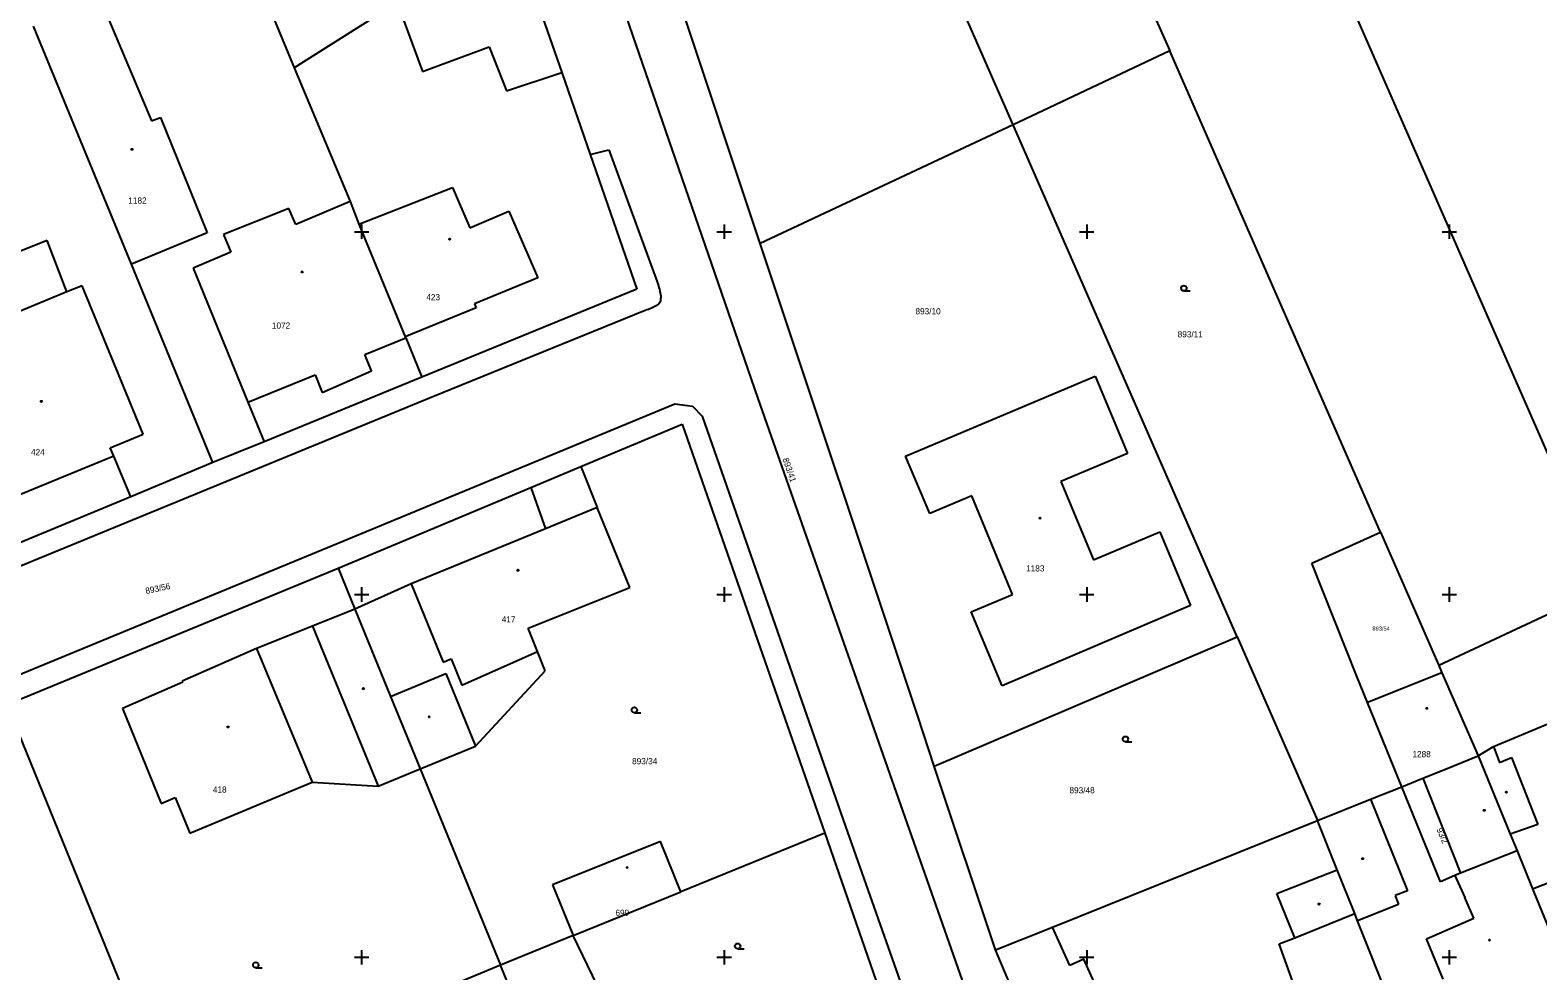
# Model space of a CAD drawing. Extents: x -711081 to -709338, y -1025122 to -1024092.
# Drawn here: x -710097.9 to -709993.9, y -1024600.9 to -1024536.1 of the extents above; entities that cross this region are included whole.
import ezdxf

# ---------------------------------------------------------------- set-up
doc = ezdxf.new("R2010")
doc.units = 0
for name, color, linetype in [('Z_hektometricka_sit', 7, 'Continuous'), ('Z_katastr_cisla_pozemkova', 7, 'Continuous'), ('Z_katastr_cisla_stavebni', 7, 'Continuous'), ('Z_katastr_hranice', 7, 'Continuous'), ('Z_katastr_hranice_katastralniho_uzemi', 7, 'Continuous'), ('Z_katastr_vnitrni_kresba', 7, 'Continuous'), ('Z_katastr_znacky_budov', 7, 'Continuous'), ('Z_katastr_znacky_kultur', 7, 'Continuous')]:
    doc.layers.add(name, color=color, linetype=linetype)

msp = doc.modelspace()

# ---------------------------------------------------------------- linework, layer by layer
at = {"layer": 'Z_hektometricka_sit'}
for p, q in [((-710075, -1024549.5), (-710075, -1024550.5)), ((-710050, -1024549.5), (-710050, -1024550.5)), ((-710025, -1024549.5), (-710025, -1024550.5)), ((-710000, -1024549.5), (-710000, -1024550.5)), ((-710075.5, -1024550), (-710074.5, -1024550)), ((-710050.5, -1024550), (-710049.5, -1024550)), ((-710025.5, -1024550), (-710024.5, -1024550)), ((-710000.5, -1024550), (-709999.5, -1024550)), ((-710075, -1024574.5), (-710075, -1024575.5)), ((-710050, -1024574.5), (-710050, -1024575.5)), ((-710025, -1024574.5), (-710025, -1024575.5)), ((-710000, -1024574.5), (-710000, -1024575.5)), ((-710075.5, -1024575), (-710074.5, -1024575)), ((-710050.5, -1024575), (-710049.5, -1024575)), ((-710025.5, -1024575), (-710024.5, -1024575)), ((-710000.5, -1024575), (-709999.5, -1024575)), ((-710075, -1024599.5), (-710075, -1024600.5)), ((-710050, -1024599.5), (-710050, -1024600.5)), ((-710025, -1024599.5), (-710025, -1024600.5)), ((-710000, -1024599.5), (-710000, -1024600.5)), ((-710075.5, -1024600), (-710074.5, -1024600)), ((-710050.5, -1024600), (-710049.5, -1024600)), ((-710025.5, -1024600), (-710024.5, -1024600)), ((-710000.5, -1024600), (-709999.5, -1024600))]:
    msp.add_line(p, q, dxfattribs=at)
at = {"layer": 'Z_katastr_hranice'}
for p, q in [((-709992.49, -1024566.92), (-710035.72, -1024468.2)), ((-710046, -1024476.54), (-710019.28, -1024537.54)), ((-710030.08, -1024542.63), (-710055.62, -1024484.15)), ((-710047.52, -1024550.81), (-710067.48, -1024490.96)), ((-710071.24, -1024493.19), (-710047.68, -1024561.5)), ((-710093.84, -1024504.36), (-710079.65, -1024538.71)), ((-710063.95, -1024531.09), (-710061.2, -1024539.03)), ((-710094.05, -1024531.53), (-710089.48, -1024542.36)), ((-710072.54, -1024534.22), (-710079.65, -1024538.71)), ((-710094.05, -1024544.53), (-710097.63, -1024535.83)), ((-710019.28, -1024537.54), (-710030.08, -1024542.63)), ((-710004.75, -1024570.7), (-710019.28, -1024537.54)), ((-710079.65, -1024538.71), (-710075.8, -1024547.92)), ((-710061.2, -1024539.03), (-710059.24, -1024544.68)), ((-710089.48, -1024542.36), (-710088.88, -1024542.12)), ((-710088.88, -1024542.12), (-710085.66, -1024550.08)), ((-710030.08, -1024542.63), (-710047.52, -1024550.81)), ((-710015.9, -1024575.01), (-710030.08, -1024542.63)), ((-710090.88, -1024552.23), (-710094.05, -1024544.53)), ((-710059.24, -1024544.68), (-710056.03, -1024553.95)), ((-710080.02, -1024548.39), (-710084.53, -1024550.19)), ((-710079.54, -1024549.5), (-710080.02, -1024548.39)), ((-710075.8, -1024547.92), (-710079.54, -1024549.5)), ((-710075.8, -1024547.92), (-710075.2, -1024549.49)), ((-710075.2, -1024549.49), (-710072, -1024557.25)), ((-710096.68, -1024550.61), (-710106.7, -1024554.58)), ((-710095.32, -1024554.15), (-710096.68, -1024550.61)), ((-710085.66, -1024550.08), (-710090.88, -1024552.23)), ((-710084.53, -1024550.19), (-710084.01, -1024551.4)), ((-710036.65, -1024583.38), (-710047.52, -1024550.81)), ((-710084.01, -1024551.4), (-710086.62, -1024552.5)), ((-710085.25, -1024565.91), (-710090.88, -1024552.23)), ((-710086.62, -1024552.5), (-710082.84, -1024561.75)), ((-710094.27, -1024553.72), (-710095.32, -1024554.15)), ((-710090.06, -1024563.94), (-710094.27, -1024553.72)), ((-710056.03, -1024553.95), (-710070.85, -1024560.03)), ((-710072, -1024557.25), (-710071.96, -1024557.32)), ((-710071.96, -1024557.32), (-710070.85, -1024560.03)), ((-710070.85, -1024560.03), (-710081.73, -1024564.47)), ((-710037.49, -1024565.47), (-710024.42, -1024559.95)), ((-710024.42, -1024559.95), (-710022.2, -1024565.28)), ((-710082.84, -1024561.75), (-710081.73, -1024564.47)), ((-710047.68, -1024561.5), (-710027.15, -1024619.89)), ((-710059.89, -1024566.18), (-710052.89, -1024563.25)), ((-710052.89, -1024563.25), (-710043.05, -1024591.45)), ((-710092.33, -1024564.88), (-710090.06, -1024563.94)), ((-710092.09, -1024565.46), (-710092.33, -1024564.88)), ((-710090.92, -1024568.26), (-710092.09, -1024565.46)), ((-710081.73, -1024564.47), (-710085.25, -1024565.91)), ((-710035.83, -1024569.41), (-710037.49, -1024565.47)), ((-710022.2, -1024565.28), (-710026.79, -1024567.2)), ((-710085.25, -1024565.91), (-710090.92, -1024568.26)), ((-710063.33, -1024567.63), (-710059.89, -1024566.18)), ((-710026.79, -1024567.2), (-710024.54, -1024572.61)), ((-710090.92, -1024568.26), (-710099.63, -1024571.88)), ((-710076.62, -1024573.19), (-710063.33, -1024567.63)), ((-710032.93, -1024568.21), (-710035.83, -1024569.41)), ((-710030.12, -1024575), (-710032.93, -1024568.21)), ((-710058.75, -1024569), (-710062.33, -1024570.47)), ((-710056.51, -1024574.51), (-710058.75, -1024569)), ((-710062.33, -1024570.47), (-710071.58, -1024574.26)), ((-710024.54, -1024572.61), (-710019.95, -1024570.69)), ((-710019.95, -1024570.69), (-710017.84, -1024575.76)), ((-710009.48, -1024572.84), (-710004.75, -1024570.7)), ((-710004.75, -1024570.7), (-710000.73, -1024579.88)), ((-710099.44, -1024582.58), (-710076.62, -1024573.19)), ((-710076.62, -1024573.19), (-710075.47, -1024576)), ((-710006.39, -1024580.59), (-710009.48, -1024572.84)), ((-710071.58, -1024574.26), (-710075.47, -1024576)), ((-710063.51, -1024577.31), (-710056.51, -1024574.51)), ((-709989.17, -1024574.48), (-710000.73, -1024579.88)), ((-710032.97, -1024576.19), (-710030.12, -1024575)), ((-710017.84, -1024575.76), (-710030.82, -1024581.3)), ((-710014.63, -1024577.91), (-710015.9, -1024575.01)), ((-710075.47, -1024576), (-710078.38, -1024577.18)), ((-710075.47, -1024576), (-710073.01, -1024582.02)), ((-710030.82, -1024581.3), (-710032.97, -1024576.19)), ((-710078.38, -1024577.18), (-710082.26, -1024578.73)), ((-710062.87, -1024578.92), (-710063.51, -1024577.31)), ((-710035.51, -1024586.82), (-710014.63, -1024577.91)), ((-710014.63, -1024577.91), (-710009.09, -1024590.57)), ((-710082.26, -1024578.73), (-710087.38, -1024580.96)), ((-710062.34, -1024580.25), (-710062.87, -1024578.92)), ((-710000.73, -1024579.88), (-710000.51, -1024580.39)), ((-710087.34, -1024581.05), (-710091.49, -1024582.86)), ((-710087.38, -1024580.96), (-710087.34, -1024581.05)), ((-710067.15, -1024585.46), (-710062.34, -1024580.25)), ((-710005.65, -1024582.45), (-710006.39, -1024580.59)), ((-710000.51, -1024580.39), (-710005.65, -1024582.45)), ((-710000.51, -1024580.39), (-709998, -1024586.11)), ((-710073.01, -1024582.02), (-710070.96, -1024587.02)), ((-710088.23, -1024610.1), (-710099.44, -1024582.58)), ((-710091.49, -1024582.86), (-710088.82, -1024589.39)), ((-710003.27, -1024588.24), (-710005.65, -1024582.45)), ((-710035.51, -1024586.82), (-710036.65, -1024583.38)), ((-710070.96, -1024587.02), (-710067.15, -1024585.46)), ((-709998, -1024586.11), (-709995.8, -1024591.51)), ((-710073.86, -1024588.21), (-710070.96, -1024587.02)), ((-710070.96, -1024587.02), (-710065.43, -1024600.53)), ((-710031.28, -1024599.49), (-710035.51, -1024586.82)), ((-710086.84, -1024591.44), (-710078.42, -1024587.93)), ((-710078.42, -1024587.93), (-710073.86, -1024588.21)), ((-710000.6, -1024594.79), (-710003.27, -1024588.24)), ((-710088.82, -1024589.39), (-710087.86, -1024588.99)), ((-710087.86, -1024588.99), (-710086.84, -1024591.44)), ((-710043.05, -1024591.45), (-710052.99, -1024595.48)), ((-710043.05, -1024591.45), (-710032.98, -1024620.44)), ((-710007.73, -1024593.97), (-710009.09, -1024590.57)), ((-710054.4, -1024592.01), (-710061.84, -1024595.01)), ((-710052.99, -1024595.48), (-710054.4, -1024592.01)), ((-709995.8, -1024591.51), (-709995.33, -1024592.66)), ((-709995.33, -1024592.66), (-709999.22, -1024594.2)), ((-709995.33, -1024592.66), (-709994.26, -1024595.27)), ((-710006.52, -1024596.99), (-710007.73, -1024593.97)), ((-709999.62, -1024594.35), (-710000.6, -1024594.79)), ((-709999.22, -1024594.2), (-709999.62, -1024594.35)), ((-710061.84, -1024595.01), (-710060.42, -1024598.5)), ((-710060.42, -1024598.5), (-710052.99, -1024595.48)), ((-709994.26, -1024595.27), (-709994.16, -1024595.52)), ((-709994.16, -1024595.52), (-709991.04, -1024603.15)), ((-710006.32, -1024597.48), (-710006.52, -1024596.99)), ((-710002.2, -1024607.77), (-710006.32, -1024597.48)), ((-710060.42, -1024598.5), (-710065.43, -1024600.53)), ((-710053.65, -1024612.42), (-710060.42, -1024598.5)), ((-710065.43, -1024600.53), (-710071.73, -1024603.17)), ((-710064.76, -1024602.17), (-710065.43, -1024600.53))]:
    msp.add_line(p, q, dxfattribs=at)
at = {"layer": 'Z_katastr_hranice_katastralniho_uzemi'}
for p, q in [((-709996.96, -1024585.48), (-709993.2, -1024583.9)), ((-709996.96, -1024585.48), (-709993.2, -1024583.9)), ((-710000.37, -1024587.07), (-709998, -1024586.11)), ((-710000.37, -1024587.07), (-709998, -1024586.11)), ((-709998, -1024586.11), (-709996.96, -1024585.48)), ((-709998, -1024586.11), (-709996.96, -1024585.48)), ((-710001.82, -1024587.65), (-710000.37, -1024587.07)), ((-710001.82, -1024587.65), (-710000.37, -1024587.07)), ((-710005.44, -1024589.11), (-710003.27, -1024588.24)), ((-710005.44, -1024589.11), (-710003.27, -1024588.24)), ((-710003.27, -1024588.24), (-710001.82, -1024587.65)), ((-710003.27, -1024588.24), (-710001.82, -1024587.65)), ((-710009.09, -1024590.57), (-710005.44, -1024589.11)), ((-710009.09, -1024590.57), (-710005.44, -1024589.11)), ((-710027.36, -1024597.92), (-710009.09, -1024590.57)), ((-710027.36, -1024597.92), (-710009.09, -1024590.57)), ((-710031.28, -1024599.49), (-710027.36, -1024597.92)), ((-710031.28, -1024599.49), (-710027.36, -1024597.92)), ((-710027.99, -1024607.28), (-710031.28, -1024599.49)), ((-710027.99, -1024607.28), (-710031.28, -1024599.49))]:
    msp.add_line(p, q, dxfattribs=at)
at = {"layer": 'Z_katastr_vnitrni_kresba'}
for p, q in [((-710072.54, -1024534.22), (-710070.8, -1024538.95)), ((-710070.8, -1024538.95), (-710066.2, -1024537.26)), ((-710066.2, -1024537.26), (-710065.02, -1024540.3)), ((-710065.02, -1024540.3), (-710061.2, -1024539.03)), ((-710059.24, -1024544.68), (-710057.96, -1024544.36)), ((-710057.96, -1024544.36), (-710054.62, -1024553.46)), ((-710075.2, -1024549.49), (-710068.74, -1024546.96)), ((-710068.74, -1024546.96), (-710067.53, -1024549.74)), ((-710067.53, -1024549.74), (-710064.84, -1024548.58)), ((-710064.84, -1024548.58), (-710062.84, -1024553.18)), ((-710062.84, -1024553.18), (-710067.21, -1024554.97)), ((-710054.62, -1024553.46), (-710054.58, -1024553.59)), ((-710054.58, -1024553.59), (-710054.54, -1024553.72)), ((-710054.54, -1024553.72), (-710054.5, -1024553.84)), ((-710054.5, -1024553.84), (-710054.46, -1024553.96)), ((-710054.46, -1024553.96), (-710054.43, -1024554.09)), ((-710095.32, -1024554.15), (-710105.21, -1024558.23)), ((-710067.21, -1024554.97), (-710067.1, -1024555.25)), ((-710054.58, -1024555.02), (-710054.65, -1024555.08)), ((-710054.51, -1024554.96), (-710054.58, -1024555.02)), ((-710054.46, -1024554.89), (-710054.51, -1024554.96)), ((-710054.42, -1024554.81), (-710054.46, -1024554.89)), ((-710054.43, -1024554.09), (-710054.41, -1024554.2)), ((-710054.39, -1024554.73), (-710054.42, -1024554.81)), ((-710054.41, -1024554.2), (-710054.39, -1024554.32)), ((-710054.39, -1024554.32), (-710054.37, -1024554.43)), ((-710054.38, -1024554.63), (-710054.39, -1024554.73)), ((-710054.37, -1024554.53), (-710054.38, -1024554.63)), ((-710054.37, -1024554.43), (-710054.37, -1024554.53)), ((-710067.1, -1024555.25), (-710072, -1024557.25)), ((-710055.45, -1024555.42), (-710070.21, -1024561.42)), ((-710055.34, -1024555.39), (-710055.45, -1024555.42)), ((-710055.23, -1024555.35), (-710055.34, -1024555.39)), ((-710055.12, -1024555.31), (-710055.23, -1024555.35)), ((-710055.02, -1024555.27), (-710055.12, -1024555.31)), ((-710054.92, -1024555.23), (-710055.02, -1024555.27)), ((-710054.82, -1024555.18), (-710054.92, -1024555.23)), ((-710054.73, -1024555.14), (-710054.82, -1024555.18)), ((-710054.65, -1024555.08), (-710054.73, -1024555.14)), ((-710074.78, -1024558.47), (-710071.96, -1024557.32)), ((-710074.33, -1024559.58), (-710074.78, -1024558.47)), ((-710082.84, -1024561.75), (-710078.21, -1024559.86)), ((-710078.21, -1024559.86), (-710077.72, -1024561.07)), ((-710077.72, -1024561.07), (-710074.33, -1024559.58)), ((-710070.21, -1024561.42), (-710108.19, -1024577.02)), ((-710077.35, -1024571.76), (-710053.41, -1024561.87)), ((-710053.41, -1024561.87), (-710052.18, -1024562.01)), ((-710052.18, -1024562.01), (-710051.52, -1024562.72)), ((-710051.52, -1024562.72), (-710041.63, -1024590.99)), ((-710092.09, -1024565.46), (-710100.77, -1024569.03)), ((-710059.89, -1024566.18), (-710058.75, -1024569)), ((-710063.33, -1024567.63), (-710062.33, -1024570.47)), ((-710105.67, -1024583.43), (-710077.35, -1024571.76)), ((-710071.58, -1024574.26), (-710069.37, -1024579.66)), ((-710078.38, -1024577.18), (-710073.86, -1024588.21)), ((-710082.26, -1024578.73), (-710078.42, -1024587.93)), ((-710068.1, -1024581.24), (-710062.87, -1024578.92)), ((-710069.37, -1024579.66), (-710068.82, -1024579.44)), ((-710068.82, -1024579.44), (-710068.1, -1024581.24)), ((-710073.01, -1024582.02), (-710069.2, -1024580.45)), ((-710069.2, -1024580.45), (-710067.15, -1024585.46)), ((-709996.96, -1024585.48), (-709996.53, -1024586.57)), ((-709996.53, -1024586.57), (-709995.71, -1024586.23)), ((-709995.71, -1024586.23), (-709993.9, -1024590.84)), ((-710001.82, -1024587.65), (-709999.22, -1024594.2)), ((-710005.44, -1024589.11), (-710002.88, -1024595.41)), ((-710041.63, -1024590.99), (-710031.4, -1024619.9)), ((-709993.9, -1024590.84), (-709995.8, -1024591.51)), ((-709994.26, -1024595.27), (-709989.12, -1024593.3)), ((-710011.88, -1024595.6), (-710007.73, -1024593.97)), ((-709999.62, -1024594.35), (-709998.92, -1024595.88)), ((-710010.65, -1024598.65), (-710011.88, -1024595.6)), ((-710002.88, -1024595.41), (-710003.73, -1024595.75)), ((-710003.49, -1024596.35), (-710006.32, -1024597.48)), ((-710003.73, -1024595.75), (-710003.49, -1024596.35)), ((-709998.3, -1024597.31), (-709998.92, -1024595.88)), ((-710010.65, -1024598.65), (-710006.52, -1024596.99)), ((-710001.58, -1024598.73), (-709998.3, -1024597.31)), ((-710026.17, -1024600.57), (-710027.36, -1024597.92)), ((-710011.74, -1024599.08), (-710010.65, -1024598.65)), ((-710000.43, -1024601.51), (-710001.58, -1024598.73)), ((-710010.57, -1024602.27), (-710011.74, -1024599.08)), ((-710025.19, -1024600.13), (-710026.17, -1024600.57)), ((-710023, -1024604.99), (-710025.19, -1024600.13))]:
    msp.add_line(p, q, dxfattribs=at)
at = {"layer": 'Z_katastr_znacky_budov'}
for centre in [(-710090.84, -1024544.32), (-710068.93, -1024550.51), (-710079.1, -1024552.77), (-710097.08, -1024561.69), (-710028.22, -1024569.74), (-710064.22, -1024573.33), (-710074.88, -1024581.48), (-710001.55, -1024582.84), (-710084.21, -1024584.13), (-710070.34, -1024583.43), (-709996.07, -1024588.62), (-709997.59, -1024589.87), (-710005.98, -1024593.2), (-710056.69, -1024593.81), (-710008.98, -1024596.33), (-709997.23, -1024598.82)]:
    msp.add_circle(centre, 0.0437, dxfattribs=at)
at = {"layer": 'Z_katastr_znacky_kultur'}
for p, q in [((-710018.3, -1024554.08), (-710017.86, -1024554.08)), ((-710056.19, -1024583.15), (-710055.75, -1024583.15)), ((-710022.33, -1024585.15), (-710021.89, -1024585.15)), ((-710049.07, -1024599.42), (-710048.63, -1024599.42)), ((-710082.3, -1024600.72), (-710081.86, -1024600.72))]:
    msp.add_line(p, q, dxfattribs=at)
for centre in [(-710018.3, -1024553.89), (-710056.19, -1024582.96), (-710022.33, -1024584.96), (-710049.07, -1024599.23), (-710082.3, -1024600.53)]:
    msp.add_circle(centre, 0.187, dxfattribs=at)

# ---------------------------------------------------------------- texts
at = {"layer": 'Z_katastr_cisla_pozemkova'}
for s, height, p in [('893/10', 0.425, (-710036.81, -1024555.69)), ('893/11', 0.425, (-710018.73, -1024557.28)), ('893/54', 0.285, (-710005.3, -1024577.49)), ('893/34', 0.425, (-710056.35, -1024586.7)), ('893/48', 0.425, (-710026.19, -1024588.7))]:
    msp.add_text(s, height=height, dxfattribs=at).set_placement(p)
for s, rotation, p in [('893/41', 289, (-710045.98, -1024565.66)), ('893/56', 12, (-710089.86, -1024574.97))]:
    msp.add_text(s, height=0.425, rotation=rotation, dxfattribs=at).set_placement(p)
at = {"layer": 'Z_katastr_cisla_stavebni'}
for s, p in [('1182', (-710091.09, -1024548.06)), ('423', (-710070.54, -1024554.72)), ('1072', (-710081.19, -1024556.68)), ('424', (-710097.8, -1024565.4)), ('1183', (-710029.18, -1024573.41)), ('417', (-710065.34, -1024576.92)), ('1288', (-710002.54, -1024586.21)), ('418', (-710085.26, -1024588.65)), ('699', (-710057.5, -1024597.14))]:
    msp.add_text(s, height=0.425, dxfattribs=at).set_placement(p)
msp.add_text('93/2', height=0.425, rotation=293, dxfattribs=at).set_placement((-710000.89, -1024591.19))

doc.saveas('drawing.dxf')
